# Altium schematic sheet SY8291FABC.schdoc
size 127 x 101 mm
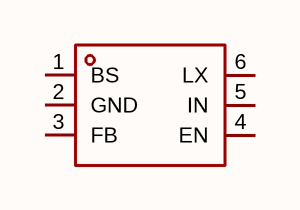
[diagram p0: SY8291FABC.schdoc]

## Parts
U?  sy8291fabc  [PG-SOT23-6_L2.9-W1.6-P0.95-LS2.8-BR]  (value not drawn)

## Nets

Not connected (* = marked no-connect by the designer): U? 1(BS) 2(GND) 3(FB) 4(EN) 5(IN) 6(LX)

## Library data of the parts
U? = sy8291fabc: 功能类型:降压型;工作电压:9V~36V;输出电压:-;输出电流:1.2A;输出类型:可调;; Manufacturer: Silergy(矽力杰); AddInBom: yes; ModelId: afbf01361280417797c9afaa50dab94a; ModelTransform: 114.173,110.236,0,90,0,0,0,0,0; Function: 降压型; Voltage - Supply: 9V~36V; Output Current: 1.2A; Frequency - Switching: 300kHz; Synchronous Rectifier: 否; Number of Outputs: 1; Topology: 降压式; Quiescent Current: 160uA; Switch tube (built-in/external): 内置; Output Type: 可调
